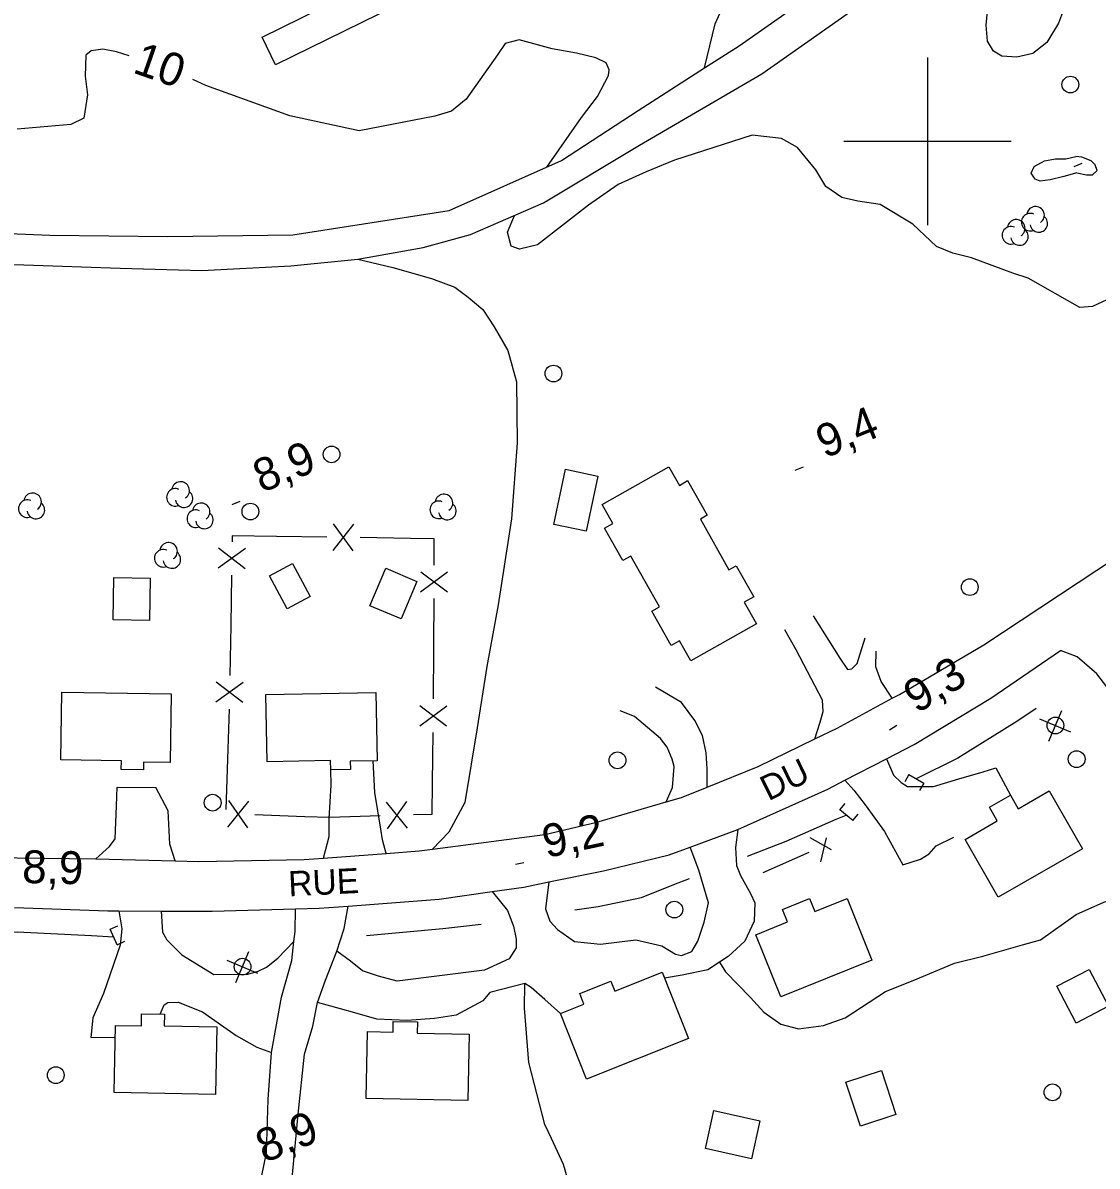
# Model space of a CAD drawing. Extents: x 362852 to 366875, y 5563573 to 5566479.
# Drawn here: x 365091.9 to 365220.3, y 5564877.5 to 5565014.2 of the extents above; entities that cross this region are included whole.
import ezdxf

# ---------------------------------------------------------------- set-up
doc = ezdxf.new("R2010")
doc.units = 0
for name, color, linetype in [('Niveau 1', 7, 'Continuous'), ('Niveau 19', 7, 'Continuous'), ('Niveau 2', 7, 'Continuous'), ('Niveau 21', 7, 'Continuous'), ('Niveau 22', 7, 'Continuous'), ('Niveau 26', 7, 'Continuous'), ('Niveau 3', 7, 'Continuous'), ('Niveau 31', 7, 'Continuous'), ('Niveau 36', 7, 'Continuous'), ('Niveau 37', 7, 'Continuous'), ('Niveau 4', 7, 'Continuous'), ('Niveau 44', 7, 'Continuous'), ('Niveau 61', 7, 'Continuous')]:
    doc.layers.add(name, color=color, linetype=linetype)

msp = doc.modelspace()

# ---------------------------------------------------------------- linework, layer by layer
at = {"layer": 'Niveau 1'}
for points in [[(365155.12, 5565011.04), (365151.2, 5565012.14), (365149.53, 5565011.7), (365148.61, 5565010.33), (365144.85, 5565005.05), (365143.1, 5565003.59), (365141.11, 5565003.01), (365132.07, 5565001.26), (365123.79, 5565003.03), (365113.75, 5565006.69), (365112.2, 5565007.37)], [(365104.58, 5565010.21), (365103.07, 5565010.7), (365101.45, 5565011.02), (365100.05, 5565010.81), (365099.4, 5565010.29), (365099.32, 5565007.78), (365099.62, 5565005.55), (365099.17, 5565002.76), (365097.62, 5565002), (365091.18, 5565001.44)], [(365154.5, 5564996.91), (365158.63, 5565002.83), (365160.55, 5565005.36), (365161.86, 5565007.88), (365161.96, 5565008.54), (365161.61, 5565009.39), (365160.37, 5565009.99), (365158.05, 5565010.52), (365155.12, 5565011.04)], [(365222.01, 5564981.35), (365219.73, 5564980.28), (365218.19, 5564980.14), (365212.03, 5564983.66), (365210.18, 5564984.26), (365205.24, 5564986.06), (365203.02, 5564986.63), (365201.08, 5564987.43), (365198.25, 5564990.1), (365194.32, 5564992.44), (365191.68, 5564992.84), (365189.77, 5564993.28), (365187.86, 5564994.6), (365186.67, 5564996.59), (365184.46, 5564999.26), (365182.54, 5565000.33), (365179.03, 5565000.73), (365169.75, 5564997.76), (365166.37, 5564996.36), (365163.03, 5564994.86), (365159.47, 5564992.39), (365153.39, 5564987.65), (365151.25, 5564987.13), (365150.25, 5564987.46), (365149.81, 5564989.14), (365150.63, 5564991.13)]]:
    msp.add_lwpolyline(points, dxfattribs=at)
at = {"layer": 'Niveau 19'}
for points in [[(365186.33, 5564943.3), (365189.51, 5564938.23), (365190.44, 5564936.87), (365190.96, 5564936.96), (365191.58, 5564937.59), (365192.55, 5564940.66)], [(365186.54, 5564928.58), (365187.17, 5564930.59), (365187.52, 5564931.86), (365187.46, 5564933.2), (365184.32, 5564939.23), (365182.93, 5564941.61)], [(365195.78, 5564933.44), (365194.44, 5564935.47), (365193.84, 5564937.21), (365193.88, 5564939.09)], [(365173.66, 5564922.83), (365173.65, 5564925), (365173.54, 5564926.93), (365173.12, 5564929.01), (365172.2, 5564930.8), (365170.59, 5564932.96), (365167.49, 5564934.78)], [(365168.76, 5564921.06), (365169.51, 5564922.78), (365169.71, 5564925.28), (365169.47, 5564926.17), (365168.88, 5564927.61), (365168.08, 5564928.64), (365164.97, 5564931.27), (365163.27, 5564931.96)], [(365135.3, 5564914.9), (365134.86, 5564916.52), (365134.65, 5564917.8), (365133.96, 5564922.19), (365133.75, 5564925.97)], [(365195.11, 5564926.22), (365195.93, 5564924.25), (365196.84, 5564923.39), (365197.6, 5564922.89), (365200.7, 5564922.92), (365203.74, 5564923.83), (365206.66, 5564924.65), (365208.18, 5564925.15), (365209.9, 5564921.86)], [(365127.81, 5564914.33), (365128.5, 5564916.93), (365128.48, 5564919.09), (365128.72, 5564923.05), (365128.67, 5564924.9)], [(365100.62, 5564914.24), (365102.25, 5564915.75), (365102.93, 5564916.65), (365103.08, 5564920.59), (365103.16, 5564922.82), (365107.76, 5564922.8)], [(365110.09, 5564914.03), (365109.44, 5564916.02), (365109.24, 5564919.99), (365107.76, 5564922.8)], [(365190.12, 5564923.64), (365191.21, 5564922.48), (365192.55, 5564920.72), (365194.86, 5564917.54), (365197.03, 5564913.53), (365199.16, 5564914.22), (365200.2, 5564914.84), (365201.04, 5564915.81), (365203.16, 5564916.83)], [(365177.34, 5564917.75), (365177.03, 5564915.6), (365177.16, 5564913.48), (365177.66, 5564912.26), (365178.86, 5564910.1), (365179.37, 5564909), (365179.3, 5564906.82), (365178.18, 5564904.44), (365176.17, 5564902.58), (365175.14, 5564901.9), (365173.76, 5564901), (365170.68, 5564900.35), (365168.55, 5564900)], [(365154.74, 5564911.5), (365154.33, 5564908.27), (365154.86, 5564906.82), (365155.77, 5564905.83), (365157.79, 5564904.37), (365160.9, 5564904.05), (365165.12, 5564904.56), (365168.23, 5564903.86), (365169.87, 5564902.85), (365170.61, 5564902.72), (365171.84, 5564903.17), (365172.55, 5564904.43), (365173.32, 5564906.71), (365173.84, 5564908.99), (365172.66, 5564912.89), (365171.62, 5564915.64)], [(365147.95, 5564910.34), (365149.81, 5564908.08), (365150.52, 5564906.21), (365150.85, 5564904.67), (365150.85, 5564903.61), (365150.01, 5564902.32), (365147.04, 5564900.96), (365136.61, 5564899.66), (365134.39, 5564900.23), (365132.46, 5564900.86), (365131.03, 5564902.02), (365129.42, 5564903.22)], [(365103.34, 5564908.04), (365103.69, 5564905.89), (365103.49, 5564903.93), (365101.5, 5564898.18), (365100.23, 5564895.24), (365100.02, 5564892.92), (365102.93, 5564892.96)], [(365108.4, 5564908.02), (365108.57, 5564905.49), (365109.07, 5564904.58), (365110.88, 5564902.8), (365114.71, 5564900.44), (365118.75, 5564900.46), (365120, 5564900.83), (365121.01, 5564901.31), (365122.37, 5564902.37), (365124.28, 5564904.38)], [(365120.38, 5564825.18), (365120.52, 5564830.45), (365120.29, 5564837.07), (365119.74, 5564844.19), (365119.05, 5564846.45), (365118.08, 5564851.64), (365117.75, 5564857.18), (365118.34, 5564863.1), (365118.9, 5564868.12), (365120.13, 5564874.86), (365120.98, 5564879.12), (365121.18, 5564885.51), (365121.58, 5564891.11), (365122.8, 5564897.73), (365124.02, 5564902.12), (365124.28, 5564904.38), (365124.41, 5564905.56), (365124.47, 5564908.29)], [(365123.46, 5564826.41), (365123.75, 5564830.3), (365123.05, 5564837.26), (365123.08, 5564842.92), (365122.4, 5564850.53), (365122.2, 5564856.6), (365122.57, 5564861.92), (365123.07, 5564867.28), (365123.68, 5564871.81), (365124.06, 5564876.1), (365124.77, 5564883.73), (365125.53, 5564890.9), (365126.55, 5564894.25), (365127.11, 5564897.09), (365128.05, 5564899.77), (365129.42, 5564903.22), (365130.28, 5564905.95), (365130.76, 5564908.62)], [(365156.12, 5564895.76), (365154.28, 5564897.46), (365152.64, 5564898.89), (365151.88, 5564899.38), (365147.67, 5564898.3), (365146.85, 5564897.28), (365143.65, 5564895.56), (365141.08, 5564895.18), (365137.78, 5564894.93), (365134.17, 5564895.09), (365131.55, 5564895.84), (365129.85, 5564896.32), (365127.11, 5564897.09)], [(365108.27, 5564895.69), (365108.77, 5564896.81), (365109.2, 5564897.11), (365110.43, 5564897.13), (365113.33, 5564895.97), (365117.38, 5564893.16), (365119.83, 5564891.75), (365121.58, 5564891.11)]]:
    msp.add_lwpolyline(points, dxfattribs=at)
at = {"layer": 'Niveau 2'}
for points in [[(365210.97, 5565020.09), (365212.03, 5565020.52), (365213.66, 5565020.46), (365214.91, 5565020.11), (365216.09, 5565018.74), (365216.58, 5565016.97), (365216.24, 5565015.71), (365215.66, 5565014.11), (365214.27, 5565011.8), (365212.59, 5565010.49), (365210.66, 5565010.06), (365208.88, 5565010.19), (365207.9, 5565010.78), (365207.17, 5565011.96), (365207, 5565013.87), (365207.17, 5565015.54), (365207.62, 5565016.84), (365208.78, 5565018.81), (365210.97, 5565020.09)], [(365217.86, 5564996.22), (365216.28, 5564995.78), (365214.64, 5564995.41), (365213.48, 5564995.24), (365212.88, 5564995.49), (365212.4, 5564996.21), (365212.76, 5564996.98), (365213.96, 5564997.67), (365215.28, 5564997.9), (365216.51, 5564997.92), (365217.72, 5564998.2)], [(365217.86, 5564996.22), (365218.99, 5564996.01), (365219.73, 5564996), (365220.26, 5564996.53), (365220.05, 5564997.19), (365219.55, 5564997.66), (365218.43, 5564998.12), (365217.72, 5564998.2)]]:
    msp.add_lwpolyline(points, dxfattribs=at)
at = {"layer": 'Niveau 21'}
for points in [[(365083.38, 5564989.28), (365095.1, 5564988.79), (365109.22, 5564988.62), (365124.14, 5564988.81), (365142.82, 5564991.73), (365156.27, 5564997.69), (365165.4, 5565003.67), (365173.36, 5565008.77), (365177.48, 5565011.41), (365188.28, 5565019), (365199.9, 5565027.14), (365209.67, 5565034.2), (365221.28, 5565042.61), (365230.31, 5565049.33), (365250.07, 5565066.31), (365253.38, 5565069.15), (365269.54, 5565081.31), (365278.94, 5565087.41), (365281.45, 5565088.05), (365282.96, 5565087.55), (365284.48, 5565085.51), (365285.56, 5565082.91), (365285.45, 5565081.81), (365285.08, 5565081.04)], [(365082.77, 5564985.48), (365092, 5564985.23), (365103.49, 5564984.84), (365113.27, 5564984.56), (365123.89, 5564985.13), (365131.92, 5564985.93), (365139.72, 5564987.31), (365145.39, 5564988.87), (365154.12, 5564992.64), (365165.58, 5564999.54), (365180.18, 5565008.07), (365195.91, 5565019.13)], [(365088.02, 5564914.41), (365100.62, 5564914.24), (365110.09, 5564914.03), (365112.9, 5564913.96), (365125.51, 5564914.16), (365127.81, 5564914.33), (365135.3, 5564914.9), (365139.26, 5564915.2), (365140.84, 5564915.41), (365154.26, 5564917.15), (365160.47, 5564918.64), (365168.76, 5564921.06), (365170.58, 5564921.59), (365173.66, 5564922.83), (365179.77, 5564925.29), (365186.54, 5564928.58), (365189.2, 5564929.88), (365195.78, 5564933.44), (365196.64, 5564933.91), (365206.71, 5564939.83), (365222.47, 5564950.23)], [(365154.74, 5564911.5), (365161.29, 5564912.82), (365169.12, 5564914.72), (365171.62, 5564915.64), (365177.34, 5564917.75), (365188.09, 5564922.6), (365190.12, 5564923.64), (365195.11, 5564926.22), (365198.39, 5564927.91), (365207.56, 5564933.46), (365215.9, 5564939.16)], [(365237.8, 5564912.75), (365231.38, 5564921.46), (365227.53, 5564926.89), (365220.22, 5564936.38), (365217.9, 5564938.4), (365215.9, 5564939.16)], [(365090.89, 5564908.43), (365102.04, 5564908.04), (365103.34, 5564908.04), (365108.4, 5564908.02), (365114.51, 5564908.01), (365124.47, 5564908.29), (365127.31, 5564908.37), (365130.76, 5564908.62), (365141.63, 5564909.42), (365147.95, 5564910.34), (365151.74, 5564910.89), (365154.74, 5564911.5)]]:
    msp.add_lwpolyline(points, dxfattribs=at)
at = {"layer": 'Niveau 22'}
for points in [[(365173.36, 5565008.77), (365174.61, 5565014.06), (365177.93, 5565021.33), (365182.36, 5565028.77), (365184.5, 5565034.24), (365184.92, 5565036.65), (365184.03, 5565042.41), (365183.63, 5565045.79), (365183.16, 5565048.87), (365183.03, 5565053.33), (365182.67, 5565057.2), (365181, 5565062.05), (365177.16, 5565067.48), (365171.51, 5565072.82), (365165.26, 5565076.41), (365163.19, 5565077.85), (365161.72, 5565079.28), (365160.7, 5565080.7), (365159.86, 5565083.01), (365159.05, 5565085.86)], [(365131.92, 5564985.93), (365136.1, 5564984.92), (365140.72, 5564983.61), (365143.5, 5564982.59), (365145.1, 5564981.37), (365146.86, 5564979.9), (365148.19, 5564977.84), (365149.83, 5564975.01), (365150.87, 5564971.27), (365150.96, 5564963.99), (365150.26, 5564954.89), (365148.67, 5564944.63), (365147.32, 5564937.23), (365146.18, 5564929.91), (365144.72, 5564921), (365142.77, 5564917.44), (365140.84, 5564915.41)], [(365175.14, 5564901.9), (365175.87, 5564900.77), (365178.83, 5564897.7), (365180.42, 5564895.95), (365182.45, 5564894.49), (365184.59, 5564893.95), (365187.56, 5564894.36), (365190.17, 5564895.25), (365194.98, 5564898.42), (365198.28, 5564899.72), (365203.24, 5564901.78), (365206.61, 5564902.61), (365211.35, 5564904), (365213.52, 5564904.59), (365217.78, 5564907.61), (365221.07, 5564909.1), (365225.75, 5564910.5), (365231.74, 5564912), (365237.8, 5564912.75)], [(365157.53, 5564874.19), (365156.49, 5564877.74), (365155.07, 5564880.83), (365154.28, 5564882.5), (365152.36, 5564889.91), (365151.85, 5564896.4), (365151.88, 5564899.38)]]:
    msp.add_lwpolyline(points, dxfattribs=at)
at = {"layer": 'Niveau 26'}
for p, q in [((365197.78, 5564924.32), (365197.3, 5564923.45)), ((365197.78, 5564924.32), (365199.54, 5564923.3)), ((365199.54, 5564923.3), (365199.03, 5564922.43)), ((365189.51, 5564920.11), (365190.14, 5564920.89)), ((365191.07, 5564918.83), (365189.51, 5564920.11)), ((365191.07, 5564918.83), (365191.7, 5564919.6)), ((365102.33, 5564905.84), (365103.24, 5564906.25)), ((365103.16, 5564904), (365102.33, 5564905.84)), ((365103.16, 5564904), (365104.07, 5564904.43))]:
    msp.add_line(p, q, dxfattribs=at)
at = {"layer": 'Niveau 3'}
for p, q in [((365217.54, 5564997.01), (365218.5, 5564997.4)), ((365184.2, 5564960.72), (365185.16, 5564961.11)), ((365116.91, 5564956.6), (365117.87, 5564956.99)), ((365195.44, 5564929.69), (365196.33, 5564930.22)), ((365150.76, 5564913.61), (365151.77, 5564913.83))]:
    msp.add_line(p, q, dxfattribs=at)
at = {"layer": 'Niveau 31'}
for points in [[(365120.46, 5565012.45), (365136.95, 5565020.57), (365138.57, 5565017.27), (365122.08, 5565009.16), (365120.46, 5565012.45)], [(365161.11, 5564956.61), (365169.09, 5564961.11), (365170.34, 5564958.89), (365171.33, 5564959.45), (365173.67, 5564955.32), (365172.85, 5564954.86), (365176.27, 5564948.81), (365177.13, 5564949.29), (365179.24, 5564945.56), (365178.1, 5564944.92), (365179.54, 5564942.36), (365171.7, 5564937.93), (365170.36, 5564940.3), (365169.36, 5564939.74), (365167.04, 5564943.85), (365167.98, 5564944.38), (365164.56, 5564950.44), (365163.59, 5564949.89), (365161.39, 5564953.79), (365162.39, 5564954.35), (365161.11, 5564956.61)], [(365160.61, 5564960), (365159.22, 5564953.4), (365155.35, 5564954.21), (365156.74, 5564960.81), (365160.61, 5564960)], [(365124.11, 5564949.55), (365126.22, 5564945.62), (365123.45, 5564944.13), (365121.34, 5564948.07), (365124.11, 5564949.55)], [(365138.98, 5564947.41), (365137.08, 5564942.94), (365133.36, 5564944.51), (365135.26, 5564948.99), (365138.98, 5564947.41)], [(365107.09, 5564947.8), (365107.02, 5564942.75), (365102.68, 5564942.81), (365102.75, 5564947.86), (365107.09, 5564947.8)], [(365096.53, 5564934.16), (365109.61, 5564933.96), (365109.49, 5564925.78), (365106.3, 5564925.83), (365106.28, 5564924.89), (365103.64, 5564924.93), (365103.66, 5564925.96), (365096.4, 5564926.07), (365096.53, 5564934.16)], [(365120.91, 5564933.88), (365134.05, 5564934.14), (365134.21, 5564925.98), (365131.01, 5564925.92), (365131.03, 5564924.94), (365128.67, 5564924.9), (365128.65, 5564925.99), (365121.07, 5564925.84), (365120.91, 5564933.88)], [(365207.39, 5564920.42), (365209.9, 5564921.86), (365210.83, 5564920.24), (365214.53, 5564922.37), (365218.51, 5564915.44), (365208.44, 5564909.66), (365204.48, 5564916.58), (365208.33, 5564918.79), (365207.39, 5564920.42)], [(365182.67, 5564908.22), (365185.89, 5564909.52), (365186.52, 5564907.96), (365190.39, 5564909.52), (365193.35, 5564902.16), (365182.46, 5564897.77), (365179.48, 5564905.19), (365183.28, 5564906.72), (365182.67, 5564908.22)], [(365217.77, 5564894.63), (365215.47, 5564899.03), (365219.33, 5564901.04), (365221.62, 5564896.64), (365217.77, 5564894.63)], [(365171.44, 5564892.77), (365159.25, 5564887.91), (365156.12, 5564895.76), (365158.93, 5564896.88), (365158.43, 5564898.15), (365162.15, 5564899.64), (365162.63, 5564898.45), (365168.27, 5564900.7), (365171.44, 5564892.77)], [(365106.07, 5564895.73), (365108.8, 5564895.68), (365108.78, 5564894.29), (365115.05, 5564894.17), (365114.89, 5564886.1), (365102.81, 5564886.33), (365102.96, 5564894.36), (365106.04, 5564894.3), (365106.07, 5564895.73)], [(365145.05, 5564885.38), (365132.89, 5564885.62), (365133.05, 5564893.61), (365136.13, 5564893.55), (365136.15, 5564894.84), (365139.04, 5564894.78), (365139.01, 5564893.42), (365145.2, 5564893.29), (365145.05, 5564885.38)], [(365194.51, 5564888.96), (365196.23, 5564883.72), (365191.98, 5564882.32), (365190.25, 5564887.56), (365194.51, 5564888.96)], [(365178.96, 5564878.42), (365173.45, 5564879.64), (365174.46, 5564884.17), (365179.97, 5564882.94), (365178.96, 5564878.42)]]:
    msp.add_lwpolyline(points, dxfattribs=at)
at = {"layer": 'Niveau 36'}
for p, q in [((365214.5, 5564928.33), (365216.05, 5564932)), ((365217.11, 5564929.39), (365213.44, 5564930.94)), ((365117.35, 5564899.5), (365118.9, 5564903.17)), ((365119.96, 5564900.56), (365116.29, 5564902.11))]:
    msp.add_line(p, q, dxfattribs=at)
for centre in [(365217.07, 5565006.78), (365155.29, 5564972.25), (365128.78, 5564962.59), (365119.07, 5564955.76), (365205.05, 5564946.73), (365215.28, 5564930.19), (365162.95, 5564926.03), (365217.82, 5564926.17), (365114.56, 5564920.97), (365169.74, 5564908.19), (365118.14, 5564901.37), (365095.81, 5564888.41), (365214.93, 5564886.36)]:
    msp.add_circle(centre, 1, dxfattribs=at)
at = {"layer": 'Niveau 37'}
for p, q in [((365128.97, 5564951.09), (365131.42, 5564954.26)), ((365131.37, 5564951.06), (365129.02, 5564954.29)), ((365128.19, 5564952.7), (365122.19, 5564952.79)), ((365138.19, 5564952.55), (365132.19, 5564952.64)), ((365118.48, 5564951.33), (365115.24, 5564948.98)), ((365118.44, 5564948.93), (365115.28, 5564951.38)), ((365116.83, 5564948.15), (365116.73, 5564942.15)), ((365139.42, 5564946.16), (365142.63, 5564948.55)), ((365139.43, 5564948.56), (365142.62, 5564946.15)), ((365116.73, 5564942.15), (365116.62, 5564936.15)), ((365140.94, 5564933.36), (365141, 5564939.36)), ((365118.2, 5564935.33), (365114.96, 5564932.98)), ((365118.16, 5564932.93), (365115, 5564935.38)), ((365139.31, 5564930.17), (365142.54, 5564932.54)), ((365139.34, 5564932.57), (365142.51, 5564930.14)), ((365116.53, 5564932.15), (365116.32, 5564926.16)), ((365140.85, 5564923.36), (365140.9, 5564929.36)), ((365116.32, 5564926.16), (365116.12, 5564920.16)), ((365118.85, 5564921.16), (365116.34, 5564918.05)), ((365116.45, 5564921.24), (365118.74, 5564917.96)), ((365135.31, 5564921.03), (365137.81, 5564917.91)), ((365137.71, 5564921.11), (365135.41, 5564917.84)), ((365119.6, 5564919.54), (365125.59, 5564919.33)), ((365125.59, 5564919.33), (365128.57, 5564919.23)), ((365128.57, 5564919.23), (365134.57, 5564919.42)), ((365185.92, 5564916.82), (365188.5, 5564915.36)), ((365187.88, 5564916.77), (365187.21, 5564913.89)), ((365180.34, 5564912.63), (365185.84, 5564915.04))]:
    msp.add_line(p, q, dxfattribs=at)
for points in [[(365122.19, 5564952.79), (365116.91, 5564952.87), (365116.9, 5564952.15)], [(365141.03, 5564949.36), (365141.04, 5564952.51), (365138.19, 5564952.55)], [(365141, 5564939.36), (365141, 5564939.84), (365141.02, 5564945.36)], [(365138.57, 5564919.54), (365140.81, 5564919.61), (365140.85, 5564923.36)]]:
    msp.add_lwpolyline(points, dxfattribs=at)
at = {"layer": 'Niveau 4'}
for points in [[(365213, 5564932.23), (365210.66, 5564930.69), (365203.61, 5564926.3), (365198.66, 5564923.81)], [(365178.5, 5564914.56), (365183.12, 5564916.37), (365189.1, 5564918.99), (365190.29, 5564919.46)], [(365157.86, 5564908.16), (365160.63, 5564908.58), (365165.83, 5564909.62), (365169.67, 5564911.19), (365171.54, 5564911.9)], [(365132.94, 5564905.08), (365142.06, 5564905.94), (365146.64, 5564906.46)], [(365102.75, 5564904.91), (365100.09, 5564905.04), (365091.21, 5564905.5), (365083.57, 5564905.38), (365080.49, 5564905.54)]]:
    msp.add_lwpolyline(points, dxfattribs=at)
at = {"layer": 'Niveau 44'}
for centre, start, end in [((365212.27, 5564990.34), 66.2054, 291.894), ((365212.91, 5564991.16), 304.3592, 171.8163), ((365209.96, 5564988.77), 66.2054, 291.894), ((365210.6, 5564989.6), 304.3592, 171.8163), ((365213.3, 5564990.19), 189.0269, 51.7112), ((365210.99, 5564988.63), 189.0269, 51.7112), ((365110.11, 5564957.45), 66.2054, 291.894), ((365110.74, 5564958.27), 304.3592, 171.8163), ((365092.41, 5564956.1), 66.2054, 291.894), ((365093.04, 5564956.92), 304.3592, 171.8163), ((365111.14, 5564957.3), 189.0269, 51.7112), ((365141.58, 5564955.97), 66.2054, 291.894), ((365142.21, 5564956.79), 304.3592, 171.8163), ((365093.44, 5564955.95), 189.0269, 51.7112), ((365112.55, 5564954.9), 66.2054, 291.894), ((365113.19, 5564955.72), 304.3592, 171.8163), ((365113.58, 5564954.76), 189.0269, 51.7112), ((365142.61, 5564955.82), 189.0269, 51.7112), ((365109.3, 5564951), 304.3592, 171.8163), ((365108.66, 5564950.18), 66.2054, 291.894), ((365109.69, 5564950.03), 189.0269, 51.7112)]:
    msp.add_arc(centre, 1.05, start, end, dxfattribs=at)
at = {"layer": 'Niveau 61'}
for p, q in [((365200, 5565010), (365200, 5564990)), ((365190, 5565000), (365210, 5565000))]:
    msp.add_line(p, q, dxfattribs=at)

# ---------------------------------------------------------------- texts
at = {"layer": 'Niveau 1'}
msp.add_text('10', height=3.93, rotation=340.7445, dxfattribs=at).set_placement((365104.87, 5565008.25))
at = {"layer": 'Niveau 21'}
for s, rotation, p in [('DU', 26.3185, (365180.98, 5564921.12)), ('RUE', 2.7902, (365123.67, 5564909.77))]:
    msp.add_text(s, height=3, rotation=rotation, dxfattribs=at).set_placement(p)
at = {"layer": 'Niveau 3'}
for s, rotation, p in [('9,4  ', 22.09, (365187.71, 5564962.08)), ('8,9  ', 22.09, (365120.42, 5564957.96)), ('9,3  ', 30.814, (365198.7, 5564931.56)), ('9,2  ', 12.1847, (365154.45, 5564914.34)), ('8,9  ', 358.6068, (365091.76, 5564911.38)), ('8,9  ', 22.09, (365120.75, 5564877.88))]:
    msp.add_text(s, height=3.93, rotation=rotation, dxfattribs=at).set_placement(p)

doc.saveas('drawing.dxf')
